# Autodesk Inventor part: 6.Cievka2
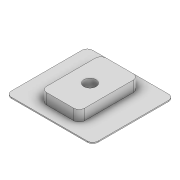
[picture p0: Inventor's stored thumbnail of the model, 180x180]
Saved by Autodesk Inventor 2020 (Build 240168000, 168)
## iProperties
Created: 2022-04
Part Number: 6.Cievka2
Material: Generic
Document SubType Name: Modeling
Designer: marti
Density: 1 g/cm^3
Appearance: Default
Author: marti
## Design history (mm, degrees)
sketch "Sketch1"
  geometry: L1 (16, 15)-(-16, 15); L2 (-16, 15)-(-16, -15); L3 (-16, -15)-(16, -15); L4 (16, -15)-(16, 15); L5 (16, 15)-(-16, -15); L6 (-16, 15)-(16, -15); 1 further point
  constraints: 12 end point, 2 midpoint, 2 parallel, 1 horizontal, 1 perpendicular
  dimensions: "d0" = 32 distance of L3.end L2.end; "d1" = 30 distance of L2.end L1.end
extrude "Extrusion1" new body sketch "Sketch1" distance "d2" = 0.4; taper "d3" = 0 deg
sketch "Sketch2"
  geometry: C1 r 2.25 at (0, 0); 1 further point
  constraints: 1 centre point, 1 coincident
  dimensions: "d4" = 4.5 diameter of C1
extrude "Extrusion2" cut sketch "Sketch2" distance "d5" = 0.4; taper "d6" = 0 deg
fillet "Fillet1" dims "d7" = 2
sketch "Sketch3"
  geometry: L1 (-7, -11)-(7, -11); L2 (7, -11)-(7, 11); L3 (7, 11)-(-7, 11); L4 (-7, 11)-(-7, -11); L5 (-7, -11)-(7, 11); L6 (7, -11)-(-7, 11); C1 r 2.25 at (0, 0) reference; C2 r 2.25 at (0, 0); 1 further point
  constraints: 12 end point, 2 midpoint, 2 parallel, 1 centre point, 1 coincident, 1 horizontal, 1 perpendicular
  dimensions: "d8" = 14 distance of L3.end L2.end; "d9" = 22 distance of L2.end L1.end
extrude "Extrusion3" join sketch "Sketch3" distance "d10" = 4; taper "d11" = 0 deg
fillet "Fillet2" dims "d12" = 2
body "Solid1"
